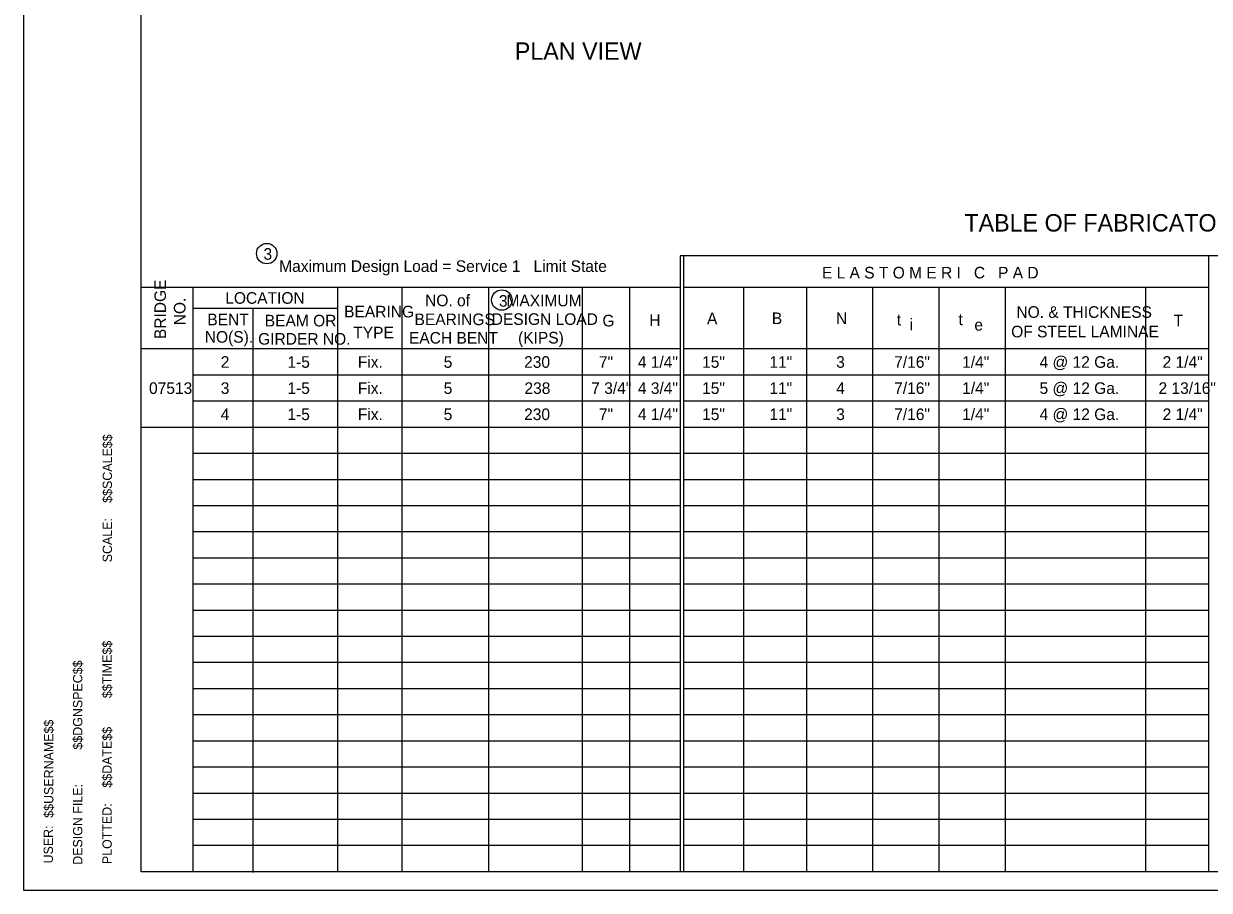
# Model space of a CAD drawing. Extents: x 32334 to 32601, y -901 to -733.
# Drawn here: x 32334.2 to 32436.3, y -900.6 to -826 of the extents above; entities that cross this region are included whole.
import ezdxf

# ---------------------------------------------------------------- set-up
doc = ezdxf.new("R2010")
doc.units = 0
for name, color, linetype in [('1', 7, 'Continuous'), ('CONC-PR$', 7, 'Continuous'), ('Level 1', 7, 'Continuous'), ('Level 63', 7, 'Continuous')]:
    doc.layers.add(name, color=color, linetype=linetype)

msp = doc.modelspace()

# ---------------------------------------------------------------- linework, layer by layer
at = {"layer": '1'}
for p, q in [((32390.71, -845.98), (32390.71, -848.72)), ((32442.28, -845.98), (32390.71, -845.98)), ((32391.01, -845.98), (32391.01, -848.72)), ((32436.18, -845.98), (32436.18, -848.72)), ((32361.22, -848.72), (32344.32, -848.72)), ((32348.77, -848.72), (32348.77, -899)), ((32361.22, -848.72), (32361.22, -899)), ((32361.22, -848.72), (32361.22, -899)), ((32390.71, -848.72), (32361.22, -848.72)), ((32366.77, -848.72), (32366.77, -899)), ((32374.22, -848.72), (32374.22, -899)), ((32382.28, -848.72), (32382.28, -899)), ((32386.35, -848.72), (32386.35, -899)), ((32390.71, -848.72), (32390.71, -899)), ((32418.98, -848.72), (32391.01, -848.72)), ((32391.01, -848.72), (32391.01, -899)), ((32396.17, -848.72), (32396.17, -899)), ((32401.58, -848.72), (32401.58, -899)), ((32401.58, -848.72), (32401.58, -899)), ((32407.28, -848.72), (32407.28, -899)), ((32412.98, -848.72), (32412.98, -899)), ((32418.69, -848.72), (32418.69, -899)), ((32436.18, -848.72), (32418.9, -848.72)), ((32430.78, -848.72), (32430.78, -899)), ((32436.18, -848.72), (32436.18, -899)), ((32361.22, -850.53), (32348.77, -850.53)), ((32353.93, -850.53), (32353.93, -899.05)), ((32348.54, -854), (32344.32, -854)), ((32361.22, -854), (32348.54, -854)), ((32390.71, -854), (32361.22, -854)), ((32430.68, -854), (32391.01, -854)), ((32436.18, -854), (32430.68, -854)), ((32361.22, -856.25), (32348.77, -856.25)), ((32390.71, -856.25), (32361.22, -856.25)), ((32430.68, -856.25), (32391.01, -856.25)), ((32436.18, -856.25), (32430.68, -856.25)), ((32361.22, -858.5), (32348.77, -858.5)), ((32390.71, -858.5), (32361.22, -858.5)), ((32430.68, -858.5), (32391.01, -858.5)), ((32436.18, -858.5), (32430.68, -858.5)), ((32361.22, -860.75), (32344.32, -860.75)), ((32390.71, -860.75), (32361.22, -860.75)), ((32430.68, -860.75), (32391.01, -860.75)), ((32436.18, -860.75), (32430.68, -860.75)), ((32361.22, -863), (32348.77, -863)), ((32390.71, -863), (32361.22, -863)), ((32430.68, -863), (32391.01, -863)), ((32436.18, -863), (32430.68, -863)), ((32361.22, -865.25), (32348.77, -865.25)), ((32390.71, -865.25), (32361.22, -865.25)), ((32430.68, -865.25), (32391.01, -865.25)), ((32436.18, -865.25), (32430.68, -865.25)), ((32361.22, -867.5), (32348.77, -867.5)), ((32390.71, -867.5), (32361.22, -867.5)), ((32430.68, -867.5), (32391.01, -867.5)), ((32436.18, -867.5), (32430.68, -867.5)), ((32361.22, -869.75), (32348.77, -869.75)), ((32390.71, -869.75), (32361.22, -869.75)), ((32430.68, -869.75), (32391.01, -869.75)), ((32436.18, -869.75), (32430.68, -869.75)), ((32361.22, -872), (32348.77, -872)), ((32390.71, -872), (32361.22, -872)), ((32430.68, -872), (32391.01, -872)), ((32436.18, -872), (32430.68, -872)), ((32361.22, -874.25), (32348.77, -874.25)), ((32390.71, -874.25), (32361.22, -874.25)), ((32430.68, -874.25), (32391.01, -874.25)), ((32436.18, -874.25), (32430.68, -874.25)), ((32361.22, -876.5), (32348.77, -876.5)), ((32390.71, -876.5), (32361.22, -876.5)), ((32430.68, -876.5), (32391.01, -876.5)), ((32436.18, -876.5), (32430.68, -876.5)), ((32361.22, -878.75), (32348.77, -878.75)), ((32390.71, -878.75), (32361.22, -878.75)), ((32430.68, -878.75), (32391.01, -878.75)), ((32436.18, -878.75), (32430.68, -878.75)), ((32361.22, -881), (32348.77, -881)), ((32390.71, -881), (32361.22, -881)), ((32430.68, -881), (32391.01, -881)), ((32436.18, -881), (32430.68, -881)), ((32361.22, -883.25), (32348.77, -883.25)), ((32390.71, -883.25), (32361.22, -883.25)), ((32430.68, -883.25), (32391.01, -883.25)), ((32436.18, -883.25), (32430.68, -883.25)), ((32361.22, -885.5), (32348.77, -885.5)), ((32390.71, -885.5), (32361.22, -885.5)), ((32430.68, -885.5), (32391.01, -885.5)), ((32436.18, -885.5), (32430.68, -885.5)), ((32361.22, -887.75), (32348.77, -887.75)), ((32390.71, -887.75), (32361.22, -887.75)), ((32430.68, -887.75), (32391.01, -887.75)), ((32436.18, -887.75), (32430.68, -887.75)), ((32361.22, -890), (32348.77, -890)), ((32390.71, -890), (32361.22, -890)), ((32430.68, -890), (32391.01, -890)), ((32436.18, -890), (32430.68, -890)), ((32361.22, -892.25), (32348.77, -892.25)), ((32390.71, -892.25), (32361.22, -892.25)), ((32430.68, -892.25), (32391.01, -892.25)), ((32436.18, -892.25), (32430.68, -892.25)), ((32361.22, -894.5), (32348.77, -894.5)), ((32390.71, -894.5), (32361.22, -894.5)), ((32430.68, -894.5), (32391.01, -894.5)), ((32436.18, -894.5), (32430.68, -894.5)), ((32361.22, -896.75), (32348.77, -896.75)), ((32390.71, -896.75), (32361.22, -896.75)), ((32430.68, -896.75), (32391.01, -896.75)), ((32436.18, -896.75), (32430.68, -896.75)), ((32390.71, -899), (32389.93, -899))]:
    msp.add_line(p, q, dxfattribs=at)
for centre in [(32355.14, -845.79), (32375.37, -849.79)]:
    msp.add_circle(centre, 0.88, dxfattribs=at)
at = {"layer": 'Level 1'}
for p, q in [((32344.32, -899), (32344.32, -734.63)), ((32597.26, -899), (32344.32, -899))]:
    msp.add_line(p, q, dxfattribs=at)
at = {"layer": 'Level 63'}
msp.add_lwpolyline([(32334.22, -900.59), (32600.86, -900.59), (32600.86, -733.02), (32334.22, -733.02)], close=True, dxfattribs=at)

# ---------------------------------------------------------------- texts
at = {"layer": '1'}
for s, height, p in [('PLAN VIEW', 1.498, (32376.49, -829.11)), ('TABLE OF FABRICATOR VARIABLES', 1.498, (32415.18, -843.89)), ('3', 1, (32354.86, -846.32)), ('Maximum Design Load = Service 1   Limit State', 1, (32356.21, -847.37)), ('E L A S T O M E R I   C   P A D', 1, (32402.92, -847.93)), ('LOCATION', 1, (32351.57, -850.11)), ('NO. of ', 1, (32368.77, -850.32)), ('3', 1, (32375.12, -850.36)), ('  MAXIMUM', 1, (32375.03, -850.33)), ('BENT', 1, (32350.03, -851.96)), ('BEARING', 1, (32361.8, -851.28)), ('BEARINGS', 1, (32367.86, -851.95)), ('DESIGN LOAD', 1, (32374.5, -851.93)), ('A', 1, (32393.03, -851.87)), ('B', 1, (32398.61, -851.86)), ('N', 1, (32404.13, -851.86)), ('NO. & THICKNESS', 1, (32419.66, -851.32)), ('BEAM OR', 1, (32354.97, -852.06)), ('G', 1, (32384.03, -852.06)), ('H', 1, (32388.06, -852.02)), ('t', 1, (32409.36, -851.98)), ('i', 1, (32410.47, -852.39)), (' t ', 1, (32414.3, -851.95)), ('e', 1, (32416.04, -852.42)), ('OF STEEL LAMINAE', 1, (32419.21, -853)), ('T', 1, (32433.18, -852.04)), ('NO(S).', 1, (32349.81, -853.46)), ('GIRDER NO.', 1, (32354.4, -853.63)), ('TYPE', 1, (32362.59, -853.09)), ('EACH BENT', 1, (32367.38, -853.54)), ('(KIPS)', 1, (32376.77, -853.53))]:
    msp.add_text(s, height=height, dxfattribs=at).set_placement(p)
for s, p in [('BRIDGE', (32346.47, -853.15)), ('NO.', (32348.15, -851.96))]:
    msp.add_text(s, height=1, rotation=90, dxfattribs=at).set_placement(p)
at = {"layer": 'CONC-PR$'}
for s, p in [('2', (32351.18, -855.62)), ('1-5', (32356.92, -855.62)), ('Fix.', (32362.98, -855.62)), ('5', (32370.37, -855.62)), ('230', (32377.29, -855.62)), ('7"', (32383.73, -855.62)), ('4 1/4"', (32387.08, -855.62)), ('15"', (32392.61, -855.62)), ('11"', (32398.4, -855.62)), ('3', (32404.15, -855.62)), ('7/16"', (32409.14, -855.62)), ('1/4"', (32414.99, -855.62)), ('4 @ 12 Ga.', (32421.65, -855.62)), ('2 1/4"', (32432.24, -855.62)), ('07513', (32345.01, -857.87)), ('3', (32351.18, -857.87)), ('1-5', (32356.92, -857.87)), ('Fix.', (32362.98, -857.87)), ('5', (32370.37, -857.87)), ('238', (32377.32, -857.87)), ('7 3/4"', (32383.07, -857.87)), ('4 3/4"', (32387.08, -857.87)), ('15"', (32392.61, -857.87)), ('11"', (32398.4, -857.87)), ('4', (32404.15, -857.87)), ('7/16"', (32409.14, -857.87)), ('1/4"', (32414.99, -857.87)), ('5 @ 12 Ga.', (32421.65, -857.87)), ('2 13/16"', (32431.89, -857.87)), ('4', (32351.18, -860.12)), ('1-5', (32356.92, -860.12)), ('Fix.', (32362.98, -860.12)), ('5', (32370.37, -860.12)), ('230', (32377.29, -860.12)), ('7"', (32383.73, -860.12)), ('4 1/4"', (32387.08, -860.12)), ('15"', (32392.61, -860.12)), ('11"', (32398.4, -860.12)), ('3', (32404.15, -860.12)), ('7/16"', (32409.14, -860.12)), ('1/4"', (32414.99, -860.12)), ('4 @ 12 Ga.', (32421.65, -860.12)), ('2 1/4"', (32432.24, -860.12))]:
    msp.add_text(s, height=1, dxfattribs=at).set_placement(p)
at = {"layer": 'Level 1'}
for s, p in [('$$SCALE$$', (32341.82, -867.24)), ('SCALE:', (32341.82, -872.36)), ('$$TIME$$', (32341.8, -884.05)), ('$$DGNSPEC$$', (32339.27, -888.48)), ('$$USERNAME$$', (32336.78, -894.35)), ('$$DATE$$', (32341.8, -891.76)), ('DESIGN FILE:', (32339.27, -898.4)), ('PLOTTED:', (32341.8, -898.34)), ('USER:', (32336.74, -898.28))]:
    msp.add_text(s, height=0.8, rotation=90, dxfattribs=at).set_placement(p)

doc.saveas('drawing.dxf')
